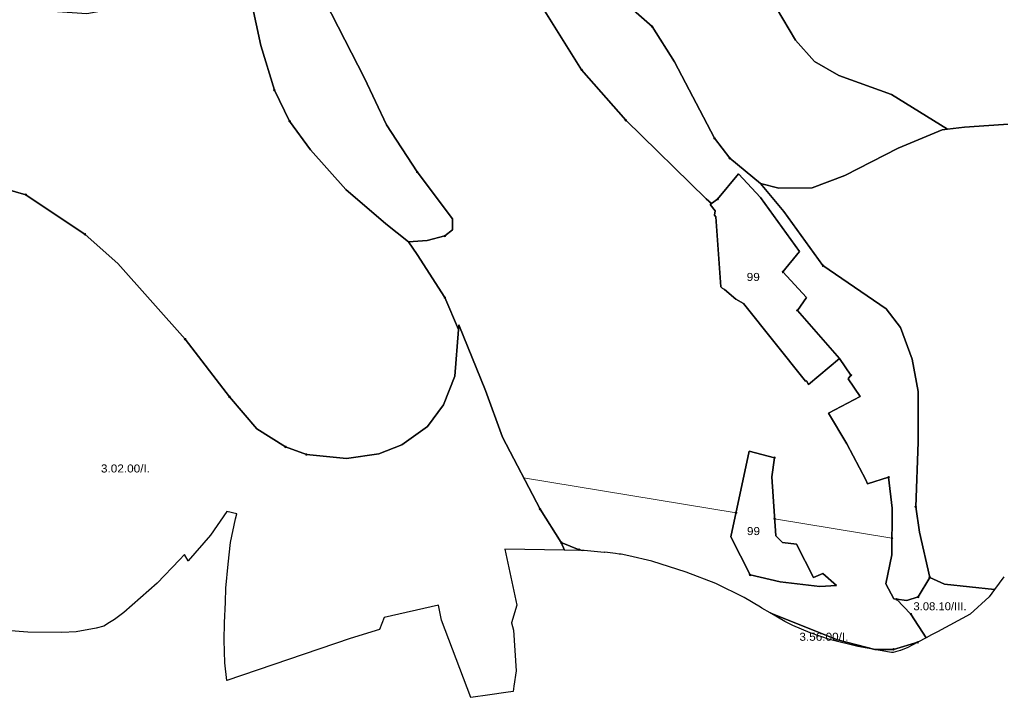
# Model space of a CAD drawing. Extents: x -650455 to -642254, y -1075222 to -1066610.
# Drawn here: x -646878 to -645652, y -1073104 to -1072257 of the extents above; entities that cross this region are included whole.
import ezdxf
from ezdxf.enums import TextEntityAlignment as Align

# ---------------------------------------------------------------- set-up
doc = ezdxf.new("R2010")
doc.units = 0
doc.header["$LTSCALE"] = 4
doc.header["$PDMODE"] = 32
doc.header["$PDSIZE"] = 2
for name, color, linetype, lineweight in [('1', 7, 'Continuous', 25), ('11', 7, 'Continuous', 13), ('13', 7, 'Continuous', 13), ('14', 7, 'Continuous', 13), ('15', 7, 'Continuous', 13), ('16', 7, 'Continuous', 13)]:
    doc.layers.add(name, color=color, linetype=linetype, lineweight=lineweight)
doc.layers.add('2', color=7, linetype='Continuous')

msp = doc.modelspace()

# ---------------------------------------------------------------- linework, layer by layer
at = {"layer": '1'}
for points in [[(-646550.686, -1071915.879), (-646559.5, -1071929.501), (-646506, -1071973.001), (-646478, -1071996), (-646472.545, -1072000), (-646448, -1072018.001), (-646420, -1072041), (-646408.5, -1072055.501), (-646389.5, -1072061.5), (-646345.4, -1072092.965), (-646345, -1072092.5), (-646296, -1072139.001), (-646248.5, -1072203), (-646175.5, -1072320), (-646120.5, -1072383.001), (-646020, -1072481), (-646013.29, -1072487.101)], [(-646908.5, -1072213.001), (-646859, -1072238.5), (-646830.5, -1072247), (-646794, -1072249.501), (-646766, -1072244.501), (-646725, -1072227.5), (-646651, -1072186), (-646624, -1072184.001), (-646611, -1072194), (-646595.5, -1072213.001), (-646588, -1072235.5), (-646576.5, -1072289.501), (-646559.5, -1072345.501), (-646540.5, -1072384), (-646514.5, -1072420.001), (-646470, -1072469.5), (-646420, -1072512.501), (-646392, -1072535), (-646381, -1072550.5), (-646346.5, -1072604.501), (-646329.469, -1072644.503), (-646334, -1072702.501), (-646348, -1072738.501), (-646368, -1072765.5)], [(-645894.5, -1072604.501), (-645924, -1072572.501), (-645903.5, -1072547), (-645952, -1072479.501), (-645979.711, -1072449.972), (-646005.6, -1072481.541), (-646013.29, -1072487.101), (-646020, -1072481), (-646120.5, -1072383.001), (-646175.5, -1072320), (-646248.5, -1072203)], [(-646504.5, -1072218), (-646447, -1072330.501), (-646419.5, -1072388.5), (-646381, -1072447.501), (-646337, -1072506), (-646337, -1072520.001), (-646346.5, -1072527.501), (-646368.5, -1072533.001), (-646392, -1072535), (-646420, -1072512.501), (-646470, -1072469.5), (-646514.5, -1072420.001), (-646540.5, -1072384), (-646559.5, -1072345.501), (-646576.5, -1072289.501), (-646588, -1072235.5)], [(-646044.852, -1072947.399), (-646087.992, -1072933.791), (-646116.558, -1072926.987), (-646126.295, -1072925.154), (-646128.552, -1072925.154), (-646133.068, -1072924.166), (-646146.615, -1072922.613), (-646147.305, -1072922.889), (-646172.567, -1072920.556), (-646174.324, -1072920.525), (-646178.5, -1072919.5), (-646201, -1072910.5), (-646227.5, -1072869.001), (-646274.5, -1072779.001), (-646295.5, -1072720.5), (-646329, -1072638.501), (-646329.469, -1072644.503), (-646346.5, -1072604.501), (-646381, -1072550.5), (-646392, -1072535), (-646368.5, -1072533.001), (-646346.5, -1072527.501), (-646337, -1072520.001), (-646337, -1072506), (-646381, -1072447.501), (-646419.5, -1072388.5), (-646447, -1072330.501), (-646504.5, -1072218)], [(-645932, -1072243), (-645908.5, -1072283), (-645884.5, -1072309.501), (-645854, -1072327), (-645788.5, -1072351.001), (-645718.5, -1072394.001), (-645725, -1072395.001), (-645780, -1072418), (-645846.5, -1072452.001), (-645887.5, -1072467.501), (-645929, -1072468.001), (-645951.948, -1072461.78), (-645990.5, -1072430.501), (-646009.5, -1072405.5), (-646059.5, -1072310.001), (-646087.5, -1072266.001), (-646128, -1072230)], [(-646128, -1072230), (-646087.5, -1072266.001), (-646059.5, -1072310.001), (-646009.5, -1072405.5), (-645990.5, -1072430.501), (-645951.948, -1072461.78), (-645923, -1072497.001), (-645874, -1072564.501), (-645795, -1072618.5), (-645777, -1072642.001), (-645762.5, -1072681.501), (-645755, -1072722.001), (-645755, -1072785), (-645758, -1072866), (-645753.5, -1072897.501), (-645740.5, -1072954.001), (-645755, -1072978.501), (-645769, -1072983), (-645781.991, -1072981.426), (-645785.5, -1072981.001), (-645795.5, -1072962.001), (-645788, -1072926.001), (-645787.5, -1072867.5), (-645792, -1072829.001), (-645818.5, -1072837.001), (-645820.5, -1072832.001), (-645844, -1072787.001), (-645867, -1072749), (-645827.5, -1072728), (-645842.5, -1072706.001), (-645839, -1072701.5), (-645853.5, -1072680.5), (-645906, -1072620.5), (-645894.5, -1072604.501)], [(-645788.5, -1072351.001), (-645854, -1072327), (-645884.5, -1072309.501), (-645908.5, -1072283), (-645932, -1072243)], [(-645594, -1072384.5), (-645697, -1072391.501), (-645718.5, -1072394.001), (-645788.5, -1072351.001)], [(-645648.03, -1072953.171), (-645659.633, -1072969.042), (-645722, -1072962.501), (-645740.5, -1072954.001), (-645753.5, -1072897.501), (-645758, -1072866), (-645755, -1072785), (-645755, -1072722.001), (-645762.5, -1072681.501), (-645777, -1072642.001), (-645795, -1072618.5), (-645874, -1072564.501), (-645923, -1072497.001), (-645951.948, -1072461.78), (-645929, -1072468.001), (-645887.5, -1072467.501), (-645846.5, -1072452.001), (-645780, -1072418), (-645725, -1072395.001), (-645718.5, -1072394.001), (-645697, -1072391.501), (-645594, -1072384.5)], [(-647197.5, -1072767.501), (-647163, -1072751.501), (-647115, -1072720.5), (-647095, -1072702.001), (-647061.5, -1072661.501), (-647051.5, -1072638.001), (-647024, -1072517.5), (-647011.5, -1072495), (-646994, -1072476.501), (-646978.5, -1072468.001), (-646949.5, -1072462), (-646909, -1072465), (-646870, -1072476.001), (-646796, -1072525.5), (-646755, -1072562), (-646671, -1072656.5), (-646615.5, -1072728.5), (-646581.5, -1072768.5), (-646545.5, -1072791.001), (-646519.5, -1072800.501)], [(-646368, -1072765.5), (-646400, -1072788.501), (-646429, -1072799.501), (-646469.5, -1072805.5), (-646519.5, -1072800.501), (-646545.5, -1072791.001), (-646581.5, -1072768.5), (-646615.5, -1072728.5), (-646671, -1072656.5), (-646755, -1072562), (-646796, -1072525.5), (-646870, -1072476.001), (-646909, -1072465)], [(-646013.29, -1072487.101), (-646015.05, -1072488.38), (-646008.85, -1072496.281), (-646009.51, -1072501.49), (-646008, -1072503.501), (-646001.5, -1072591), (-645999.77, -1072592.6), (-645996.89, -1072594.561), (-645982.84, -1072606.461), (-645973.45, -1072611.73), (-645895.91, -1072708.97), (-645894.58, -1072708.52), (-645891.891, -1072712.988), (-645853.5, -1072680.5), (-645839, -1072701.5), (-645842.5, -1072706.001), (-645827.5, -1072728), (-645867, -1072749), (-645844, -1072787.001), (-645820.5, -1072832.001), (-645818.5, -1072837.001), (-645792, -1072829.001), (-645787.5, -1072867.5), (-645788, -1072926.001), (-645795.5, -1072962.001), (-645785.5, -1072981.001), (-645781.991, -1072981.426), (-645764, -1073000), (-645744.901, -1073029.348), (-645755.631, -1073035.068), (-645786, -1073044), (-645809, -1073044), (-645856, -1073032), (-645936, -1073000), (-645940.001, -1072998.4), (-645950.335, -1072992.289), (-645951.835, -1072991.39), (-645972.369, -1072979.088), (-646007.736, -1072961.59), (-646044.852, -1072947.399)], [(-646519.5, -1072800.501), (-646469.5, -1072805.5), (-646429, -1072799.501), (-646400, -1072788.501), (-646368, -1072765.5), (-646348, -1072738.501), (-646334, -1072702.501), (-646329.469, -1072644.503), (-646329, -1072638.501), (-646295.5, -1072720.5), (-646274.5, -1072779.001), (-646227.5, -1072869.001), (-646201, -1072910.5), (-646197.074, -1072920.127), (-646271.37, -1072918.83), (-646256.628, -1072988.933), (-646263.043, -1073010.896), (-646260.47, -1073020.003), (-646257.448, -1073070.811), (-646260.097, -1073090), (-646261.077, -1073096.462), (-646270.039, -1073097.707), (-646290.434, -1073100.596), (-646313.957, -1073103.929), (-646350.634, -1073007.419), (-646354.291, -1072988.654), (-646422.376, -1073004.025), (-646427.959, -1073018.939), (-646464.927, -1073030.328), (-646619.029, -1073082.989), (-646621.552, -1073060.665), (-646622.395, -1073032.266), (-646621.615, -1073010.769), (-646620.678, -1072984.937), (-646620.049, -1072967.628), (-646617.063, -1072937.311), (-646614.405, -1072910.337), (-646608.196, -1072880.702), (-646606.34, -1072874.563), (-646618.894, -1072871.868)], [(-646618.894, -1072871.868), (-646639.36, -1072901.265), (-646667.031, -1072933.353), (-646671.949, -1072925.375), (-646678.069, -1072932.215), (-646705.921, -1072961.063), (-646747.701, -1072997.867), (-646759.354, -1073006.536), (-646765.283, -1073010.32), (-646772.712, -1073015.062), (-646781.949, -1073017.62), (-646806.959, -1073022.026), (-646825.149, -1073022.879), (-646867.497, -1073022.31), (-646894.212, -1073020.321)]]:
    msp.add_lwpolyline(points, dxfattribs=at)
for points in [[(-645853.5, -1072680.5), (-645891.891, -1072712.988), (-645894.58, -1072708.52), (-645895.91, -1072708.97), (-645973.45, -1072611.73), (-645982.84, -1072606.461), (-645996.89, -1072594.561), (-645999.77, -1072592.6), (-646001.5, -1072591), (-646008, -1072503.501), (-646009.51, -1072501.49), (-646008.85, -1072496.281), (-646015.05, -1072488.38), (-646013.29, -1072487.101), (-646005.6, -1072481.541), (-645979.711, -1072449.972), (-645952, -1072479.501), (-645903.5, -1072547), (-645924, -1072572.501), (-645894.5, -1072604.501), (-645906, -1072620.5)], [(-645907, -1072912.501), (-645886, -1072954.001), (-645874, -1072949.001), (-645857, -1072964), (-645878, -1072965.501), (-645927.5, -1072959.5), (-645965, -1072951), (-645989, -1072903.5), (-645966, -1072796.501), (-645934.5, -1072804.501), (-645938, -1072828.501), (-645933, -1072902), (-645924.5, -1072910.5)], [(-645907, -1072912.501), (-645924.5, -1072910.5), (-645933, -1072902), (-645938, -1072828.501), (-645934.5, -1072804.501), (-645966, -1072796.501), (-645989, -1072903.5), (-645965, -1072951), (-645927.5, -1072959.5), (-645878, -1072965.501), (-645857, -1072964), (-645874, -1072949.001), (-645886, -1072954.001)], [(-646178.5, -1072919.5), (-646174.324, -1072920.525), (-646197.074, -1072920.127), (-646201, -1072910.5)], [(-645666.315, -1072978.183), (-645690.151, -1073000.05), (-645730.916, -1073021.894), (-645738.336, -1073025.848), (-645744.901, -1073029.348), (-645764, -1073000), (-645781.991, -1072981.426), (-645769, -1072983), (-645755, -1072978.501), (-645740.5, -1072954.001), (-645722, -1072962.501), (-645659.633, -1072969.042)], [(-645856, -1073032), (-645809, -1073044), (-645786, -1073044), (-645755.631, -1073035.068), (-645767.974, -1073041.649), (-645777.06, -1073045.328), (-645777.396, -1073045.416), (-645783.246, -1073046.95), (-645786.145, -1073047.71), (-645788.257, -1073047.659), (-645790.688, -1073047.601), (-645830.275, -1073040.566), (-645865.968, -1073031.798), (-645889.98, -1073023.354), (-645911.829, -1073014.261), (-645921.78, -1073009.174), (-645940.001, -1072998.4), (-645936, -1073000)]]:
    msp.add_lwpolyline(points, close=True, dxfattribs=at)
at = {"layer": '11'}
for p, q in [((-646870, -1072476.001), (-646909, -1072465)), ((-646615.5, -1072728.5), (-646671, -1072656.5)), ((-646519.5, -1072800.501), (-646545.5, -1072791.001))]:
    msp.add_line(p, q, dxfattribs=at)
for points in [[(-646929.643, -1071786.538), (-646870.396, -1071861.944), (-646758.889, -1072000), (-646757.286, -1072001.985), (-646709, -1072113.5), (-646673, -1072147.501), (-646624, -1072184.001), (-646611, -1072194), (-646595.5, -1072213.001), (-646588, -1072235.5), (-646576.5, -1072289.501), (-646559.5, -1072345.501), (-646540.5, -1072384)], [(-646346.5, -1072527.501), (-646337, -1072520.001), (-646337, -1072506), (-646381, -1072447.501), (-646419.5, -1072388.5), (-646447, -1072330.501), (-646504.5, -1072218), (-646584, -1072105.5)], [(-646027.5, -1072126), (-646011, -1072139.501), (-645967.5, -1072184.501), (-645932, -1072243), (-645908.5, -1072283), (-645884.5, -1072309.501), (-645854, -1072327), (-645788.5, -1072351.001), (-645718.5, -1072394.001), (-645697, -1072391.501), (-645594, -1072384.5), (-645567.5, -1072387.001), (-645560, -1072390.001), (-645550.5, -1072338.001), (-645549, -1072189.5), (-645544.5, -1072153.5), (-645532, -1072135.501), (-645510.5, -1072118.5), (-645474.5, -1072111.501), (-645421, -1072113), (-645398, -1072117), (-645373.5, -1072126), (-645338.5, -1072147.001)], [(-646559.5, -1072345.501), (-646576.5, -1072289.501), (-646588, -1072235.5), (-646595.5, -1072213.001), (-646611, -1072194), (-646624, -1072184.001), (-646651, -1072186), (-646725, -1072227.5)], [(-646346.5, -1072604.501), (-646381, -1072550.5), (-646392, -1072535), (-646420, -1072512.501), (-646470, -1072469.5), (-646514.5, -1072420.001), (-646540.5, -1072384), (-646559.5, -1072345.501)], [(-646540.5, -1072384), (-646514.5, -1072420.001), (-646470, -1072469.5), (-646420, -1072512.501), (-646392, -1072535), (-646368.5, -1072533.001), (-646346.5, -1072527.501)], [(-647083, -1072482.5), (-647052.5, -1072495.501), (-647024, -1072517.5), (-647011.5, -1072495), (-646994, -1072476.501), (-646978.5, -1072468.001), (-646949.5, -1072462), (-646909, -1072465), (-646870, -1072476.001), (-646796, -1072525.5)], [(-646671, -1072656.5), (-646755, -1072562), (-646796, -1072525.5), (-646870, -1072476.001)], [(-646796, -1072525.5), (-646755, -1072562), (-646671, -1072656.5), (-646615.5, -1072728.5), (-646581.5, -1072768.5), (-646545.5, -1072791.001), (-646519.5, -1072800.501), (-646469.5, -1072805.5), (-646429, -1072799.501), (-646400, -1072788.501), (-646368, -1072765.5), (-646348, -1072738.501), (-646334, -1072702.501), (-646329.469, -1072644.503), (-646346.5, -1072604.501)], [(-646227.5, -1072869.001), (-646274.5, -1072779.001), (-646295.5, -1072720.5), (-646329, -1072638.501), (-646329.469, -1072644.503), (-646334, -1072702.501), (-646348, -1072738.501), (-646368, -1072765.5), (-646400, -1072788.501), (-646429, -1072799.501), (-646469.5, -1072805.5), (-646519.5, -1072800.501)], [(-646545.5, -1072791.001), (-646581.5, -1072768.5), (-646615.5, -1072728.5)], [(-646894.212, -1073020.321), (-646867.497, -1073022.31), (-646825.149, -1073022.879), (-646806.959, -1073022.026), (-646781.949, -1073017.62), (-646772.712, -1073015.062), (-646765.283, -1073010.32), (-646759.354, -1073006.536), (-646747.701, -1072997.867), (-646705.921, -1072961.063), (-646678.069, -1072932.215), (-646671.949, -1072925.375), (-646667.031, -1072933.353), (-646639.36, -1072901.265), (-646618.894, -1072871.868), (-646606.34, -1072874.563), (-646608.196, -1072880.702), (-646614.405, -1072910.337), (-646617.063, -1072937.311), (-646620.049, -1072967.628), (-646620.678, -1072984.937), (-646621.615, -1073010.769), (-646622.395, -1073032.266), (-646621.552, -1073060.665), (-646619.029, -1073082.989), (-646464.927, -1073030.328), (-646427.959, -1073018.939), (-646422.376, -1073004.025), (-646354.291, -1072988.654)], [(-646354.291, -1072988.654), (-646350.634, -1073007.419), (-646313.957, -1073103.929), (-646290.434, -1073100.596), (-646270.039, -1073097.707), (-646261.077, -1073096.462), (-646260.097, -1073090), (-646257.448, -1073070.811), (-646260.47, -1073020.003), (-646263.043, -1073010.896), (-646256.628, -1072988.933), (-646271.37, -1072918.83), (-646197.074, -1072920.127), (-646201, -1072910.5), (-646227.5, -1072869.001)], [(-645786, -1073044), (-645809, -1073044), (-645856, -1073032), (-645936, -1073000), (-645940.001, -1072998.4), (-645921.78, -1073009.174), (-645911.829, -1073014.261), (-645889.98, -1073023.354), (-645865.968, -1073031.798)], [(-645865.968, -1073031.798), (-645830.275, -1073040.566), (-645790.688, -1073047.601), (-645788.257, -1073047.659), (-645786.145, -1073047.71), (-645783.246, -1073046.95), (-645777.396, -1073045.416), (-645777.06, -1073045.328), (-645767.974, -1073041.649), (-645755.631, -1073035.068), (-645786, -1073044)]]:
    msp.add_lwpolyline(points, dxfattribs=at)
for p in [(-646559.5, -1072345.501), (-646540.5, -1072384), (-646870, -1072476.001), (-646796, -1072525.5), (-646346.5, -1072527.501), (-646346.5, -1072604.501), (-646671, -1072656.5), (-646615.5, -1072728.5), (-646545.5, -1072791.001), (-646519.5, -1072800.501), (-646227.5, -1072869.001), (-645786, -1073044)]:
    msp.add_point(p, dxfattribs=at)
at = {"layer": '13'}
msp.add_line((-645874, -1072564.501), (-645795, -1072618.5), dxfattribs=at)
for points in [[(-646128, -1072230), (-646087.5, -1072266.001)], [(-646009.5, -1072405.5), (-645990.5, -1072430.501), (-645951.948, -1072461.78), (-645929, -1072468.001), (-645887.5, -1072467.501), (-645846.5, -1072452.001), (-645780, -1072418), (-645725, -1072395.001), (-645718.5, -1072394.001), (-645788.5, -1072351.001), (-645854, -1072327), (-645884.5, -1072309.501), (-645908.5, -1072283), (-645932, -1072243)], [(-646087.5, -1072266.001), (-646059.5, -1072310.001), (-646009.5, -1072405.5)], [(-645594, -1072384.5), (-645697, -1072391.501), (-645718.5, -1072394.001), (-645725, -1072395.001), (-645780, -1072418), (-645846.5, -1072452.001), (-645887.5, -1072467.501), (-645929, -1072468.001), (-645951.948, -1072461.78), (-645923, -1072497.001), (-645874, -1072564.501)], [(-645795, -1072618.5), (-645777, -1072642.001), (-645762.5, -1072681.501), (-645755, -1072722.001), (-645755, -1072785), (-645758, -1072866), (-645753.5, -1072897.501), (-645740.5, -1072954.001)], [(-645740.5, -1072954.001), (-645722, -1072962.501), (-645659.633, -1072969.042), (-645648.03, -1072953.171)]]:
    msp.add_lwpolyline(points, dxfattribs=at)
msp.add_lwpolyline([(-645744.901, -1073029.348), (-645738.336, -1073025.848), (-645730.916, -1073021.894), (-645690.151, -1073000.05), (-645666.315, -1072978.183), (-645659.633, -1072969.042), (-645722, -1072962.501), (-645740.5, -1072954.001), (-645755, -1072978.501), (-645769, -1072983), (-645781.991, -1072981.426), (-645764, -1073000)], close=True, dxfattribs=at)
for p in [(-646009.5, -1072405.5), (-645874, -1072564.501), (-645740.5, -1072954.001)]:
    msp.add_point(p, dxfattribs=at)
at = {"layer": '14'}
for p, q in [((-646120.5, -1072383.001), (-646175.5, -1072320)), ((-646201, -1072910.5), (-646178.5, -1072919.5)), ((-645764, -1073000), (-645781.991, -1072981.426))]:
    msp.add_line(p, q, dxfattribs=at)
for points in [[(-646577.5, -1072041), (-646604, -1072062.501), (-646584, -1072105.5), (-646504.5, -1072218), (-646447, -1072330.501), (-646419.5, -1072388.5), (-646381, -1072447.501)], [(-646175.5, -1072320), (-646248.5, -1072203), (-646296, -1072139.001)], [(-645787.821, -1072905.039), (-645787.5, -1072867.5), (-645792, -1072829.001), (-645818.5, -1072837.001), (-645820.5, -1072832.001), (-645844, -1072787.001), (-645867, -1072749), (-645827.5, -1072728), (-645842.5, -1072706.001), (-645839, -1072701.5), (-645853.5, -1072680.5), (-645891.891, -1072712.988), (-645894.58, -1072708.52), (-645895.91, -1072708.97), (-645973.45, -1072611.73), (-645982.84, -1072606.461), (-645996.89, -1072594.561), (-645999.77, -1072592.6), (-646001.5, -1072591), (-646008, -1072503.501), (-646009.51, -1072501.49), (-646008.85, -1072496.281), (-646015.05, -1072488.38), (-646013.29, -1072487.101), (-646020, -1072481), (-646120.5, -1072383.001)], [(-646381, -1072447.501), (-646337, -1072506), (-646337, -1072520.001), (-646346.5, -1072527.501), (-646368.5, -1072533.001), (-646392, -1072535), (-646381, -1072550.5), (-646346.5, -1072604.501), (-646329.469, -1072644.503), (-646329, -1072638.501), (-646295.5, -1072720.5), (-646274.5, -1072779.001), (-646248.012, -1072829.723), (-645982.483, -1072873.18)], [(-645982.483, -1072873.18), (-645966, -1072796.501), (-645934.5, -1072804.501), (-645938, -1072828.501), (-645934.426, -1072881.045), (-645787.821, -1072905.039)], [(-645781.991, -1072981.426), (-645785.5, -1072981.001), (-645795.5, -1072962.001), (-645788, -1072926.001), (-645787.821, -1072905.039), (-645934.426, -1072881.045), (-645933, -1072902), (-645924.5, -1072910.5), (-645907, -1072912.501), (-645886, -1072954.001), (-645874, -1072949.001), (-645857, -1072964), (-645878, -1072965.501), (-645927.5, -1072959.5), (-645965, -1072951), (-645989, -1072903.5), (-645982.483, -1072873.18), (-646248.012, -1072829.723), (-646227.5, -1072869.001), (-646201, -1072910.5)], [(-646178.5, -1072919.5), (-646174.324, -1072920.525), (-646172.567, -1072920.556), (-646147.305, -1072922.889), (-646146.615, -1072922.613), (-646133.068, -1072924.166), (-646128.552, -1072925.154), (-646126.295, -1072925.154), (-646116.558, -1072926.987), (-646087.992, -1072933.791), (-646044.852, -1072947.399), (-646007.736, -1072961.59), (-645972.369, -1072979.088), (-645951.835, -1072991.39), (-645950.335, -1072992.289), (-645940.001, -1072998.4), (-645936, -1073000), (-645856, -1073032), (-645809, -1073044), (-645786, -1073044), (-645755.631, -1073035.068)], [(-645755.631, -1073035.068), (-645744.901, -1073029.348), (-645764, -1073000)]]:
    msp.add_lwpolyline(points, dxfattribs=at)
for p in [(-646175.5, -1072320), (-646120.5, -1072383.001), (-646381, -1072447.501), (-645982.483, -1072873.18), (-646201, -1072910.5), (-645787.821, -1072905.039), (-646178.5, -1072919.5), (-645781.991, -1072981.426), (-645764, -1073000), (-645755.631, -1073035.068)]:
    msp.add_point(p, dxfattribs=at)
at = {"layer": '15'}
msp.add_line((-645755, -1072978.501), (-645740.5, -1072954.001), dxfattribs=at)
for points in [[(-646087.5, -1072266.001), (-646128, -1072230), (-646179, -1072180.501), (-646227, -1072108.5)], [(-646248.5, -1072203), (-646175.5, -1072320), (-646120.5, -1072383.001), (-646020, -1072481), (-646013.29, -1072487.101), (-646005.6, -1072481.541), (-645979.711, -1072449.972), (-645952, -1072479.501), (-645903.5, -1072547), (-645924, -1072572.501)], [(-645990.5, -1072430.501), (-646009.5, -1072405.5), (-646059.5, -1072310.001), (-646087.5, -1072266.001)], [(-645874, -1072564.501), (-645923, -1072497.001), (-645951.948, -1072461.78), (-645990.5, -1072430.501)], [(-645758, -1072866), (-645755, -1072785), (-645755, -1072722.001), (-645762.5, -1072681.501), (-645777, -1072642.001), (-645795, -1072618.5), (-645874, -1072564.501)], [(-645924, -1072572.501), (-645894.5, -1072604.501), (-645906, -1072620.5), (-645853.5, -1072680.5), (-645839, -1072701.5)], [(-645839, -1072701.5), (-645842.5, -1072706.001), (-645827.5, -1072728), (-645867, -1072749), (-645844, -1072787.001), (-645820.5, -1072832.001), (-645818.5, -1072837.001), (-645792, -1072829.001)], [(-645792, -1072829.001), (-645787.5, -1072867.5), (-645787.821, -1072905.039), (-645788, -1072926.001), (-645795.5, -1072962.001), (-645785.5, -1072981.001), (-645781.991, -1072981.426)], [(-645740.5, -1072954.001), (-645753.5, -1072897.501), (-645758, -1072866)], [(-645781.991, -1072981.426), (-645769, -1072983), (-645755, -1072978.501)]]:
    msp.add_lwpolyline(points, dxfattribs=at)
for p in [(-646087.5, -1072266.001), (-645990.5, -1072430.501), (-645924, -1072572.501), (-645874, -1072564.501), (-645839, -1072701.5), (-645792, -1072829.001), (-645758, -1072866), (-645740.5, -1072954.001), (-645781.991, -1072981.426), (-645755, -1072978.501)]:
    msp.add_point(p, dxfattribs=at)
at = {"layer": '16'}
for points in [[(-645906, -1072620.5), (-645894.5, -1072604.501), (-645924, -1072572.501), (-645903.5, -1072547), (-645952, -1072479.501), (-645979.711, -1072449.972), (-646005.6, -1072481.541)], [(-646005.6, -1072481.541), (-646013.29, -1072487.101), (-646015.05, -1072488.38), (-646008.85, -1072496.281), (-646009.51, -1072501.49), (-646008, -1072503.501), (-646001.5, -1072591)], [(-646001.5, -1072591), (-645999.77, -1072592.6), (-645996.89, -1072594.561), (-645982.84, -1072606.461), (-645973.45, -1072611.73), (-645895.91, -1072708.97), (-645894.58, -1072708.52), (-645891.891, -1072712.988), (-645853.5, -1072680.5), (-645906, -1072620.5)], [(-645934.5, -1072804.501), (-645966, -1072796.501), (-645989, -1072903.5), (-645965, -1072951)], [(-645934.426, -1072881.045), (-645938, -1072828.501), (-645934.5, -1072804.501)], [(-645965, -1072951), (-645927.5, -1072959.5), (-645878, -1072965.501), (-645857, -1072964), (-645874, -1072949.001), (-645886, -1072954.001), (-645907, -1072912.501), (-645924.5, -1072910.5), (-645933, -1072902), (-645934.426, -1072881.045)]]:
    msp.add_lwpolyline(points, dxfattribs=at)
for p in [(-646005.6, -1072481.541), (-645906, -1072620.5), (-645934.5, -1072804.501), (-645934.426, -1072881.045), (-645965, -1072951)]:
    msp.add_point(p, dxfattribs=at)

# ---------------------------------------------------------------- texts
at = {"layer": '2'}
for s, width, p in [('99', 1.1, (-645961.093, -1072583.68)), ('3.02.00/I.', 1.1, (-646745.524, -1072822.982)), ('99', 1.1, (-645960.785, -1072901.18)), ('3.08.10/III.', 1.05, (-645727.731, -1072995.105)), ('3.56.00/I.', 1.1, (-645872.789, -1073033.186))]:
    msp.add_text(s, height=10, dxfattribs=dict(at, width=width)).set_placement(p, align=Align.CENTER)

doc.saveas('drawing.dxf')
